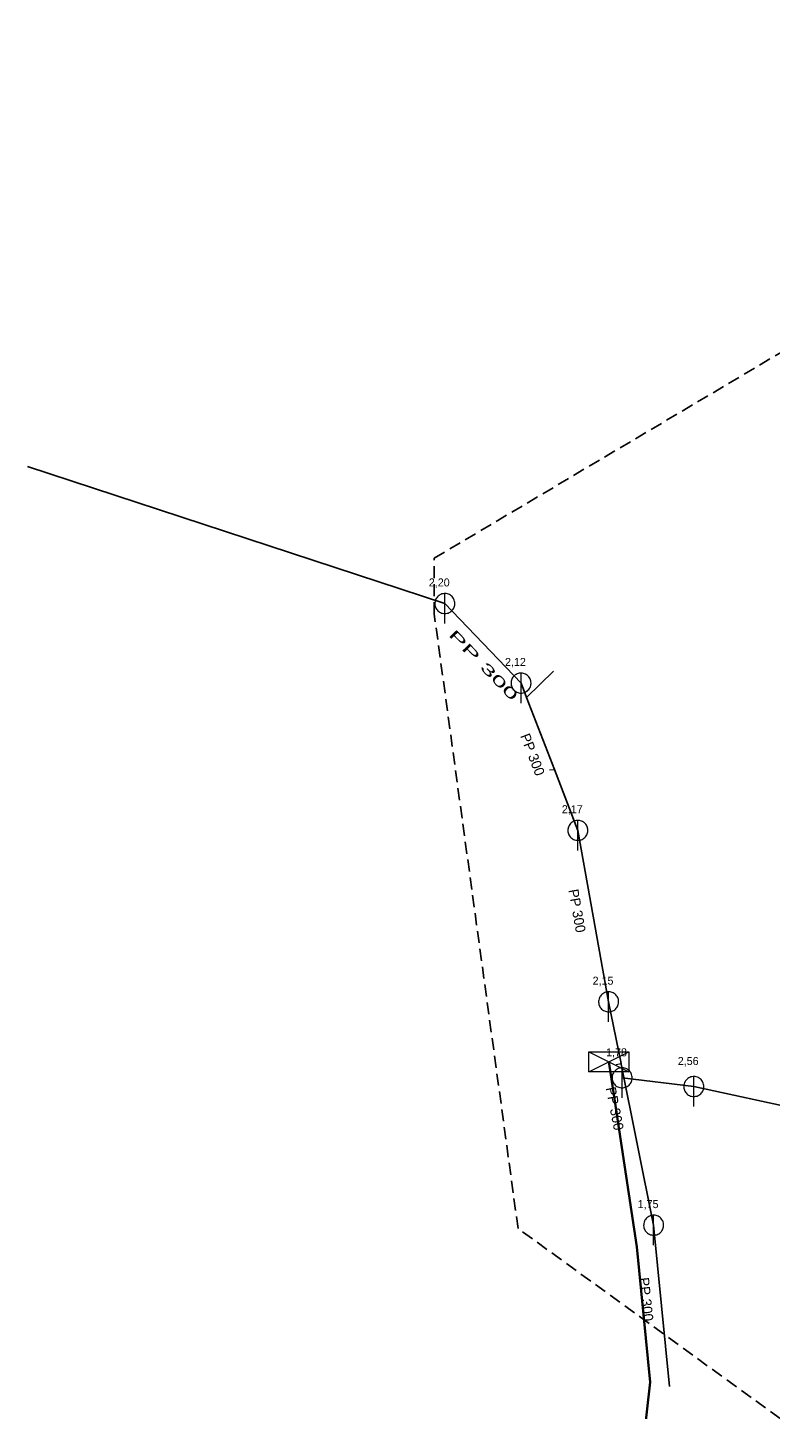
# Model space of a CAD drawing. Extents: x -683466 to -682479, y -996772 to -995963.
# Drawn here: x -683465.9 to -683391.7, y -996101.3 to -995963.2 of the extents above; entities that cross this region are included whole.
import ezdxf

# ---------------------------------------------------------------- set-up
doc = ezdxf.new("R2010")
doc.units = 0
doc.header["$LTSCALE"] = 0.4
doc.linetypes.add('MEDIUM_DASHED', pattern=[4.5, 3, -1.5])
doc.layers.add('1', color=7, linetype='Continuous')
for name, color, linetype, lineweight in [('11', 7, 'Continuous', 13), ('14', 7, 'Continuous', 25), ('19', 7, 'Continuous', 13), ('22', 7, 'Continuous', 13), ('63', 7, 'MEDIUM_DASHED', 25)]:
    doc.layers.add(name, color=color, linetype=linetype, lineweight=lineweight)

msp = doc.modelspace()

# ---------------------------------------------------------------- linework, layer by layer
at = {"layer": '11'}
for p, q in [((-683413.359, -996027.559), (-683416.05, -996030.19)), ((-683413.78, -996037.41), (-683413.28, -996037.379)), ((-683407.112, -996066.859), (-683406.613, -996066.774))]:
    msp.add_line(p, q, dxfattribs=at)
at = {"layer": '11', "lineweight": 35}
msp.add_lwpolyline([(-683407.84, -996066.598), (-683407.342, -996069.868), (-683405.052, -996085.105), (-683403.697, -996098.614), (-683405.789, -996116.999), (-683406.748, -996131.568), (-683407.708, -996134.633), (-683408.835, -996135.985), (-683413.158, -996137.298), (-683416.684, -996144.513), (-683422.749, -996164.237), (-683429.769, -996184.829), (-683431.912, -996188.158), (-683434.649, -996186.649), (-683435.35, -996187.445)], dxfattribs=at)
at = {"layer": '14'}
for p, q in [((-683399.35, -996069.07), (-683406.51, -996068.199)), ((-683374.48, -996074.48), (-683399.35, -996069.07)), ((-683403.359, -996082.93), (-683401.76, -996099.05))]:
    msp.add_line(p, q, dxfattribs=at)
for points in [[(-683465.899, -996007.1), (-683424.219, -996020.789), (-683416.609, -996028.739)], [(-683416.609, -996028.739), (-683416.05, -996030.19), (-683413.28, -996037.379), (-683410.93, -996043.46), (-683407.859, -996060.6)], [(-683407.859, -996060.6), (-683406.613, -996066.774), (-683406.6, -996066.84), (-683403.359, -996082.93)]]:
    msp.add_lwpolyline(points, dxfattribs=at)
at = {"layer": '19'}
for p, q in [((-683409.841, -996067.607), (-683405.838, -996065.589)), ((-683409.841, -996065.589), (-683405.838, -996067.607))]:
    msp.add_line(p, q, dxfattribs=at)
msp.add_lwpolyline([(-683409.841, -996065.589), (-683405.838, -996065.589), (-683405.838, -996067.607), (-683409.841, -996067.607)], close=True, dxfattribs=at)
at = {"layer": '22'}
for p, q in [((-683424.22, -996022.79), (-683424.219, -996019.79)), ((-683416.61, -996030.74), (-683416.609, -996027.74)), ((-683410.93, -996045.46), (-683410.929, -996042.46)), ((-683407.86, -996062.6), (-683407.859, -996059.6)), ((-683406.51, -996070.199), (-683406.509, -996067.199)), ((-683399.35, -996071.07), (-683399.349, -996068.07)), ((-683403.36, -996084.93), (-683403.359, -996081.93))]:
    msp.add_line(p, q, dxfattribs=at)
for points in [[(-683423.22, -996020.79), (-683423.225, -996020.681), (-683423.243, -996020.573), (-683423.273, -996020.467), (-683423.313, -996020.366), (-683423.365, -996020.269), (-683423.427, -996020.179), (-683423.499, -996020.096), (-683423.579, -996020.022), (-683423.667, -996019.956), (-683423.761, -996019.901), (-683423.861, -996019.856), (-683423.966, -996019.823), (-683424.073, -996019.801), (-683424.182, -996019.791), (-683424.292, -996019.793), (-683424.4, -996019.807), (-683424.507, -996019.832), (-683424.61, -996019.869), (-683424.708, -996019.918), (-683424.8, -996019.976), (-683424.886, -996020.045), (-683424.963, -996020.122), (-683425.032, -996020.208), (-683425.091, -996020.3), (-683425.139, -996020.398), (-683425.176, -996020.501), (-683425.202, -996020.608), (-683425.216, -996020.716), (-683425.219, -996020.826), (-683425.209, -996020.935), (-683425.188, -996021.042), (-683425.154, -996021.146), (-683425.11, -996021.246), (-683425.055, -996021.341), (-683424.989, -996021.429), (-683424.915, -996021.509), (-683424.832, -996021.581), (-683424.742, -996021.643), (-683424.646, -996021.695), (-683424.544, -996021.736), (-683424.439, -996021.766), (-683424.331, -996021.784), (-683424.221, -996021.79), (-683424.112, -996021.784), (-683424.004, -996021.766), (-683423.899, -996021.737), (-683423.797, -996021.696), (-683423.7, -996021.644), (-683423.61, -996021.582), (-683423.527, -996021.511), (-683423.452, -996021.431), (-683423.387, -996021.343), (-683423.331, -996021.249), (-683423.287, -996021.149), (-683423.253, -996021.045), (-683423.231, -996020.937), (-683423.221, -996020.828)], [(-683415.61, -996028.74), (-683415.615, -996028.631), (-683415.633, -996028.523), (-683415.663, -996028.417), (-683415.703, -996028.316), (-683415.755, -996028.219), (-683415.817, -996028.129), (-683415.889, -996028.046), (-683415.969, -996027.972), (-683416.057, -996027.906), (-683416.151, -996027.851), (-683416.251, -996027.806), (-683416.356, -996027.773), (-683416.463, -996027.751), (-683416.572, -996027.741), (-683416.682, -996027.743), (-683416.79, -996027.757), (-683416.897, -996027.782), (-683417, -996027.819), (-683417.098, -996027.868), (-683417.19, -996027.926), (-683417.276, -996027.995), (-683417.353, -996028.072), (-683417.422, -996028.158), (-683417.481, -996028.25), (-683417.529, -996028.348), (-683417.566, -996028.451), (-683417.592, -996028.558), (-683417.606, -996028.666), (-683417.609, -996028.776), (-683417.599, -996028.885), (-683417.578, -996028.992), (-683417.544, -996029.096), (-683417.5, -996029.196), (-683417.445, -996029.291), (-683417.379, -996029.379), (-683417.305, -996029.459), (-683417.222, -996029.531), (-683417.132, -996029.593), (-683417.036, -996029.645), (-683416.934, -996029.686), (-683416.829, -996029.716), (-683416.721, -996029.734), (-683416.611, -996029.74), (-683416.502, -996029.734), (-683416.394, -996029.716), (-683416.289, -996029.687), (-683416.187, -996029.646), (-683416.09, -996029.594), (-683416, -996029.532), (-683415.917, -996029.461), (-683415.842, -996029.381), (-683415.777, -996029.293), (-683415.721, -996029.199), (-683415.677, -996029.099), (-683415.643, -996028.995), (-683415.621, -996028.887), (-683415.611, -996028.778)], [(-683409.93, -996043.46), (-683409.935, -996043.351), (-683409.953, -996043.243), (-683409.983, -996043.137), (-683410.023, -996043.036), (-683410.075, -996042.939), (-683410.137, -996042.849), (-683410.209, -996042.766), (-683410.289, -996042.692), (-683410.377, -996042.626), (-683410.471, -996042.571), (-683410.571, -996042.526), (-683410.676, -996042.493), (-683410.783, -996042.471), (-683410.892, -996042.461), (-683411.002, -996042.463), (-683411.11, -996042.477), (-683411.217, -996042.502), (-683411.32, -996042.539), (-683411.418, -996042.588), (-683411.51, -996042.646), (-683411.596, -996042.715), (-683411.673, -996042.792), (-683411.742, -996042.878), (-683411.801, -996042.97), (-683411.849, -996043.068), (-683411.886, -996043.171), (-683411.912, -996043.278), (-683411.926, -996043.386), (-683411.929, -996043.496), (-683411.919, -996043.605), (-683411.898, -996043.712), (-683411.864, -996043.816), (-683411.82, -996043.916), (-683411.765, -996044.011), (-683411.699, -996044.099), (-683411.625, -996044.179), (-683411.542, -996044.251), (-683411.452, -996044.313), (-683411.356, -996044.365), (-683411.254, -996044.406), (-683411.149, -996044.436), (-683411.041, -996044.454), (-683410.931, -996044.46), (-683410.822, -996044.454), (-683410.714, -996044.436), (-683410.609, -996044.407), (-683410.507, -996044.366), (-683410.41, -996044.314), (-683410.32, -996044.252), (-683410.237, -996044.181), (-683410.162, -996044.101), (-683410.097, -996044.013), (-683410.041, -996043.919), (-683409.997, -996043.819), (-683409.963, -996043.715), (-683409.941, -996043.607), (-683409.931, -996043.498)], [(-683406.86, -996060.6), (-683406.865, -996060.491), (-683406.883, -996060.383), (-683406.913, -996060.277), (-683406.953, -996060.176), (-683407.005, -996060.079), (-683407.067, -996059.989), (-683407.139, -996059.906), (-683407.219, -996059.832), (-683407.307, -996059.766), (-683407.401, -996059.711), (-683407.501, -996059.666), (-683407.606, -996059.633), (-683407.713, -996059.611), (-683407.822, -996059.601), (-683407.932, -996059.603), (-683408.04, -996059.617), (-683408.147, -996059.642), (-683408.25, -996059.679), (-683408.348, -996059.728), (-683408.44, -996059.786), (-683408.526, -996059.855), (-683408.603, -996059.932), (-683408.672, -996060.018), (-683408.731, -996060.11), (-683408.779, -996060.208), (-683408.816, -996060.311), (-683408.842, -996060.418), (-683408.856, -996060.526), (-683408.859, -996060.636), (-683408.849, -996060.745), (-683408.828, -996060.852), (-683408.794, -996060.956), (-683408.75, -996061.056), (-683408.695, -996061.151), (-683408.629, -996061.239), (-683408.555, -996061.319), (-683408.472, -996061.391), (-683408.382, -996061.453), (-683408.286, -996061.505), (-683408.184, -996061.546), (-683408.079, -996061.576), (-683407.971, -996061.594), (-683407.861, -996061.6), (-683407.752, -996061.594), (-683407.644, -996061.576), (-683407.539, -996061.547), (-683407.437, -996061.506), (-683407.34, -996061.454), (-683407.25, -996061.392), (-683407.167, -996061.321), (-683407.092, -996061.241), (-683407.027, -996061.153), (-683406.971, -996061.059), (-683406.927, -996060.959), (-683406.893, -996060.855), (-683406.871, -996060.747), (-683406.861, -996060.638)], [(-683405.51, -996068.199), (-683405.515, -996068.09), (-683405.533, -996067.982), (-683405.563, -996067.876), (-683405.603, -996067.775), (-683405.655, -996067.678), (-683405.717, -996067.588), (-683405.789, -996067.505), (-683405.869, -996067.431), (-683405.957, -996067.365), (-683406.051, -996067.31), (-683406.151, -996067.265), (-683406.256, -996067.232), (-683406.363, -996067.21), (-683406.472, -996067.2), (-683406.582, -996067.202), (-683406.69, -996067.216), (-683406.797, -996067.241), (-683406.9, -996067.278), (-683406.998, -996067.327), (-683407.09, -996067.385), (-683407.176, -996067.454), (-683407.253, -996067.531), (-683407.322, -996067.617), (-683407.381, -996067.709), (-683407.429, -996067.807), (-683407.466, -996067.91), (-683407.492, -996068.017), (-683407.506, -996068.125), (-683407.509, -996068.235), (-683407.499, -996068.344), (-683407.478, -996068.451), (-683407.444, -996068.555), (-683407.4, -996068.655), (-683407.345, -996068.75), (-683407.279, -996068.838), (-683407.205, -996068.918), (-683407.122, -996068.99), (-683407.032, -996069.052), (-683406.936, -996069.104), (-683406.834, -996069.145), (-683406.729, -996069.175), (-683406.621, -996069.193), (-683406.511, -996069.199), (-683406.402, -996069.193), (-683406.294, -996069.175), (-683406.189, -996069.146), (-683406.087, -996069.105), (-683405.99, -996069.053), (-683405.9, -996068.991), (-683405.817, -996068.92), (-683405.742, -996068.84), (-683405.677, -996068.752), (-683405.621, -996068.658), (-683405.577, -996068.558), (-683405.543, -996068.454), (-683405.521, -996068.346), (-683405.511, -996068.237)], [(-683398.35, -996069.07), (-683398.355, -996068.961), (-683398.373, -996068.853), (-683398.403, -996068.747), (-683398.443, -996068.646), (-683398.495, -996068.549), (-683398.557, -996068.459), (-683398.629, -996068.376), (-683398.709, -996068.302), (-683398.797, -996068.236), (-683398.891, -996068.181), (-683398.991, -996068.136), (-683399.096, -996068.103), (-683399.203, -996068.081), (-683399.312, -996068.071), (-683399.422, -996068.073), (-683399.53, -996068.087), (-683399.637, -996068.112), (-683399.74, -996068.149), (-683399.838, -996068.198), (-683399.93, -996068.256), (-683400.016, -996068.325), (-683400.093, -996068.402), (-683400.162, -996068.488), (-683400.221, -996068.58), (-683400.269, -996068.678), (-683400.306, -996068.781), (-683400.332, -996068.888), (-683400.346, -996068.996), (-683400.349, -996069.106), (-683400.339, -996069.215), (-683400.318, -996069.322), (-683400.284, -996069.426), (-683400.24, -996069.526), (-683400.185, -996069.621), (-683400.119, -996069.709), (-683400.045, -996069.789), (-683399.962, -996069.861), (-683399.872, -996069.923), (-683399.776, -996069.975), (-683399.674, -996070.016), (-683399.569, -996070.046), (-683399.461, -996070.064), (-683399.351, -996070.07), (-683399.242, -996070.064), (-683399.134, -996070.046), (-683399.029, -996070.017), (-683398.927, -996069.976), (-683398.83, -996069.924), (-683398.74, -996069.862), (-683398.657, -996069.791), (-683398.582, -996069.711), (-683398.517, -996069.623), (-683398.461, -996069.529), (-683398.417, -996069.429), (-683398.383, -996069.325), (-683398.361, -996069.217), (-683398.351, -996069.108)], [(-683402.36, -996082.93), (-683402.365, -996082.821), (-683402.383, -996082.713), (-683402.413, -996082.607), (-683402.453, -996082.506), (-683402.505, -996082.409), (-683402.567, -996082.319), (-683402.639, -996082.236), (-683402.719, -996082.162), (-683402.807, -996082.096), (-683402.901, -996082.041), (-683403.001, -996081.996), (-683403.106, -996081.963), (-683403.213, -996081.941), (-683403.322, -996081.931), (-683403.432, -996081.933), (-683403.54, -996081.947), (-683403.647, -996081.972), (-683403.75, -996082.009), (-683403.848, -996082.058), (-683403.94, -996082.116), (-683404.026, -996082.185), (-683404.103, -996082.262), (-683404.172, -996082.348), (-683404.231, -996082.44), (-683404.279, -996082.538), (-683404.316, -996082.641), (-683404.342, -996082.748), (-683404.356, -996082.856), (-683404.359, -996082.966), (-683404.349, -996083.075), (-683404.328, -996083.182), (-683404.294, -996083.286), (-683404.25, -996083.386), (-683404.195, -996083.481), (-683404.129, -996083.569), (-683404.055, -996083.649), (-683403.972, -996083.721), (-683403.882, -996083.783), (-683403.786, -996083.835), (-683403.684, -996083.876), (-683403.579, -996083.906), (-683403.471, -996083.924), (-683403.361, -996083.93), (-683403.252, -996083.924), (-683403.144, -996083.906), (-683403.039, -996083.877), (-683402.937, -996083.836), (-683402.84, -996083.784), (-683402.75, -996083.722), (-683402.667, -996083.651), (-683402.592, -996083.571), (-683402.527, -996083.483), (-683402.471, -996083.389), (-683402.427, -996083.289), (-683402.393, -996083.185), (-683402.371, -996083.077), (-683402.361, -996082.968)]]:
    msp.add_lwpolyline(points, close=True, dxfattribs=at)
at = {"layer": '63'}
msp.add_lwpolyline([(-683425.281, -996021.839), (-683425.281, -996016.256), (-683425.281, -996016.256), (-683335.962, -995963.223), (-683335.962, -995963.223), (-682479.059, -996630.324), (-682479.059, -996630.324), (-682551.631, -996711.269), (-682551.631, -996711.269), (-683416.907, -996083.246), (-683416.907, -996083.246)], close=True, dxfattribs=at)

# ---------------------------------------------------------------- texts
at = {"layer": '1'}
for s, p in [('2,20', (-683425.819, -996019.078)), ('2,12', (-683418.209, -996027.028)), ('2,17', (-683412.529, -996041.748)), ('2,15', (-683409.459, -996058.888)), ('1,78', (-683408.11, -996066.047)), ('2,56', (-683400.949, -996066.917)), ('1,75', (-683404.959, -996081.218))]:
    msp.add_text(s, height=0.8, dxfattribs=at).set_placement(p)
at = {"layer": '1', "width": 2.1}
msp.add_text('PP 300', height=1, rotation=314, dxfattribs=at).set_placement((-683423.922, -996023.97))
at = {"layer": '1'}
for rotation, p in [(291, (-683416.705, -996034.016)), (280, (-683411.877, -996049.426)), (281, (-683408.147, -996069.215)), (276, (-683404.83, -996088.2))]:
    msp.add_text('PP 300', height=1, rotation=rotation, dxfattribs=at).set_placement(p)

doc.saveas('drawing.dxf')
